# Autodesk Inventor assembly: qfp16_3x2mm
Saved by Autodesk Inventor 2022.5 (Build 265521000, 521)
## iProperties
Created: 2024-12
Part Number: qfp16_3x2mm
Document SubType Name: Assembly
Designer: AdminForWorker
Title: qfp16_3x2mm v1
Author: AdminForWorker
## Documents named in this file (3)
- c:\worker\convert-fusion-r05-cosv3\tmp\job-1\35\temp\files\545dca92-a972-481a-9197-dd1a1176500e\qfp16_3x2mm v1.iam
- c:\worker\convert-fusion-r05-cosv3\tmp\job-1\35\temp\files\545dca92-a972-481a-9197-dd1a1176500e\Component1.ipt
- c:\worker\convert-fusion-r05-cosv3\tmp\job-1\35\temp\files\545dca92-a972-481a-9197-dd1a1176500e\lead.ipt
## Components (2 placed, 2 different names)
1. Component1:1
2. lead:1
